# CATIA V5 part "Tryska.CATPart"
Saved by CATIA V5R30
Part number: Tryska
Definition: EH 4200_37_SMM_1
Nomenclature: EH 4200_37_SMM_1
Source: Unknown
Description: PART-EH 4200_37_SMM_1-DESC
Bounding box of the stored display mesh (mm): x -100.85 to -79.15, y -10.848 to 10.848, z -39.3 to 0.7
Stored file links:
  E:\Bakalarka\Model\Forma_v7\Tryska.CATPart
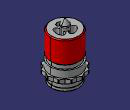
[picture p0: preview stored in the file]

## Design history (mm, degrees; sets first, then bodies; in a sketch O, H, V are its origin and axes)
Body1 "MANIFOLD_SOLID_BREP #3554" (main body)
  Solid1: solid without history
